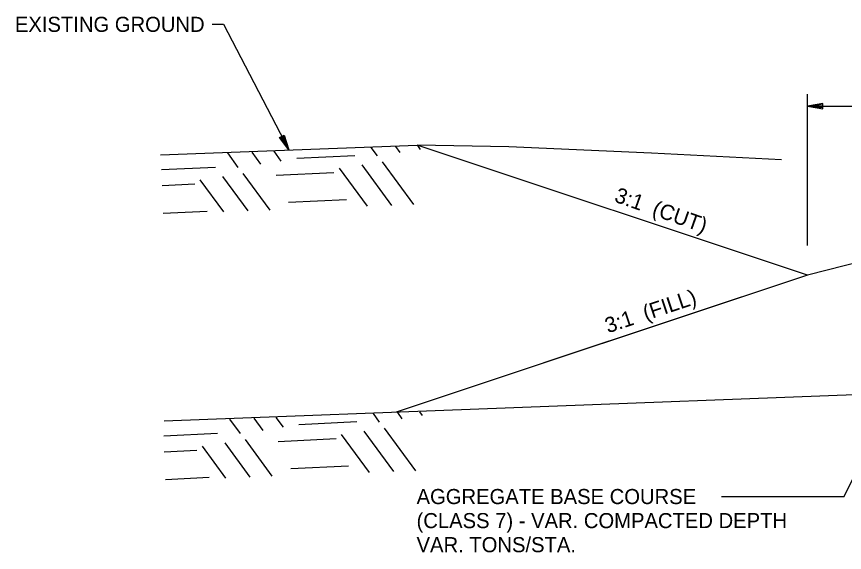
# Model space of a CAD drawing. Extents: x 1398183 to 1398373, y 1967240 to 1968889.
# Drawn here: x 1398192.21 to 1398224.54, y 1967244.68 to 1967265.61 of the extents above; entities that cross this region are included whole.
import ezdxf

# ---------------------------------------------------------------- set-up
doc = ezdxf.new("R2010")
doc.units = 0
for name, color, linetype in [('10', 7, 'Continuous'), ('19', 7, 'Continuous'), ('20', 7, 'Continuous'), ('42', 7, 'Continuous'), ('9', 7, 'Continuous')]:
    doc.layers.add(name, color=color, linetype=linetype)

msp = doc.modelspace()

# ---------------------------------------------------------------- linework, layer by layer
at = {"layer": '19'}
for p, q in [((1398223.096, 1967262.116), (1398232.096, 1967262.116)), ((1398202.475, 1967260.889), (1398202.66, 1967260.985)), ((1398202.844, 1967260.405), (1398202.475, 1967260.889)), ((1398202.762, 1967260.541), (1398202.525, 1967260.909)), ((1398202.621, 1967260.96), (1398202.783, 1967260.554)), ((1398202.66, 1967260.985), (1398202.844, 1967260.405)), ((1398223.096, 1967255.519), (1398207.86, 1967260.597)), ((1398231.096, 1967257.519), (1398223.096, 1967255.519)), ((1398224.535, 1967246.873), (1398229.161, 1967256.376)), ((1398223.096, 1967255.519), (1398207.03, 1967250.163)), ((1398223.096, 1967255.519), (1398212.795, 1967252.085)), ((1398219.737, 1967246.873), (1398224.535, 1967246.873))]:
    msp.add_line(p, q, dxfattribs=at)
msp.add_lwpolyline([(1398199.845, 1967265.311), (1398200.291, 1967265.311), (1398202.844, 1967260.405)], dxfattribs=at)
at = {"layer": '20'}
for p, q in [((1398223.096, 1967256.665), (1398223.096, 1967262.577)), ((1398223.696, 1967262.221), (1398223.096, 1967262.116)), ((1398223.096, 1967262.116), (1398223.696, 1967262.011)), ((1398223.696, 1967262.166), (1398223.256, 1967262.131)), ((1398223.256, 1967262.101), (1398223.696, 1967262.061)), ((1398223.696, 1967262.011), (1398223.696, 1967262.221))]:
    msp.add_line(p, q, dxfattribs=at)
at = {"layer": '42'}
for points in [[(1398197.828, 1967260.212), (1398207.86, 1967260.597)], [(1398222.081, 1967260.014), (1398217.01, 1967260.283), (1398211.438, 1967260.53), (1398207.86, 1967260.597)], [(1398197.974, 1967249.816), (1398225.288, 1967250.864)]]:
    msp.add_lwpolyline(points, dxfattribs=at)
at = {"layer": '9'}
for p, q in [((1398206.307, 1967260.174), (1398206.065, 1967260.504)), ((1398207.192, 1967260.301), (1398207.017, 1967260.541)), ((1398207.986, 1967260.425), (1398207.876, 1967260.574)), ((1398200.869, 1967259.721), (1398200.456, 1967260.286)), ((1398201.755, 1967259.848), (1398201.407, 1967260.323)), ((1398202.548, 1967259.972), (1398202.267, 1967260.356)), ((1398205.416, 1967260.176), (1398203.157, 1967260.07)), ((1398206.864, 1967258.239), (1398205.708, 1967259.816)), ((1398207.723, 1967258.272), (1398206.501, 1967259.94)), ((1398199.979, 1967259.724), (1398197.875, 1967259.625)), ((1398202.114, 1967258.054), (1398201.064, 1967259.487)), ((1398204.607, 1967259.514), (1398202.347, 1967259.407)), ((1398205.912, 1967258.202), (1398204.823, 1967259.689)), ((1398200.303, 1967257.984), (1398199.385, 1967259.237)), ((1398201.255, 1967258.021), (1398200.271, 1967259.364)), ((1398199.17, 1967259.061), (1398197.899, 1967259.001)), ((1398205.093, 1967258.456), (1398202.834, 1967258.35)), ((1398199.656, 1967258.003), (1398197.941, 1967257.923)), ((1398206.389, 1967249.775), (1398206.147, 1967250.105)), ((1398207.275, 1967249.902), (1398207.099, 1967250.142)), ((1398208.068, 1967250.026), (1398207.958, 1967250.175)), ((1398200.952, 1967249.322), (1398200.538, 1967249.887)), ((1398201.838, 1967249.449), (1398201.49, 1967249.924)), ((1398202.631, 1967249.573), (1398202.349, 1967249.957)), ((1398205.499, 1967249.777), (1398203.239, 1967249.671)), ((1398207.806, 1967247.873), (1398206.584, 1967249.541)), ((1398200.061, 1967249.325), (1398197.958, 1967249.226)), ((1398204.69, 1967249.115), (1398202.43, 1967249.008)), ((1398205.995, 1967247.803), (1398204.905, 1967249.29)), ((1398206.947, 1967247.84), (1398205.791, 1967249.417)), ((1398200.386, 1967247.585), (1398199.468, 1967248.838)), ((1398201.338, 1967247.622), (1398200.354, 1967248.965)), ((1398202.197, 1967247.655), (1398201.147, 1967249.088)), ((1398199.252, 1967248.662), (1398197.982, 1967248.602)), ((1398205.176, 1967248.057), (1398202.916, 1967247.951)), ((1398199.739, 1967247.605), (1398198.024, 1967247.524))]:
    msp.add_line(p, q, dxfattribs=at)

# ---------------------------------------------------------------- texts
at = {"layer": '10'}
msp.add_text('EXISTING GROUND', height=0.59001, dxfattribs=at).set_placement((1398192.147, 1967265.016))
at = {"layer": '19'}
for s, p in [('AGGREGATE BASE COURSE', (1398207.832, 1967246.57)), ('(CLASS 7) - VAR. COMPACTED DEPTH', (1398207.832, 1967245.63)), ('VAR. TONS/STA.', (1398207.832, 1967244.69))]:
    msp.add_text(s, height=0.59001, rotation=360, dxfattribs=at).set_placement(p)
at = {"layer": '42'}
for s, rotation, p in [('3:1  (CUT)', 340.4943, (1398215.521, 1967258.395)), ('3:1  (FILL)', 18.4349, (1398215.306, 1967253.238))]:
    msp.add_text(s, height=0.6, rotation=rotation, dxfattribs=at).set_placement(p)

doc.saveas('drawing.dxf')
